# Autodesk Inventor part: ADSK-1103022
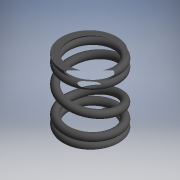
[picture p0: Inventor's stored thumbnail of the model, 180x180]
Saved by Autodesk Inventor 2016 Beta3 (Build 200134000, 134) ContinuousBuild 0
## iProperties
Shininess: 24.0
Length Units: 11272
Angle Units: 11279
Time Units: 11290
Mass Units: 11286
Length Display Precision: 4
Angle Display Precision: 2
Compacted: True
Created: 2000-03
Part Number: ADSK-1103022
Document SubType Name: Modeling
Description: UHAN SPRING #334-2
Mass: 0.0822308 g
Surface Area: 0.886826 cm^2
Volume: 0.0101771 cm^3
Density: 8.08 g/cm^3
Material: Stainless Steel
Appearance: Black
Density: 0.0
Volumn: 0.0
Area: 0.0
PropertySet Name: Model Information
Control State: 0
Master: False
Checked Out: False
Author: Autodesk, Inc.
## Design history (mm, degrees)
sketch "Sketch2"
  geometry: L1 (-14.979, -10.854)-(-14.979, 14.546); A1 r 0.254 centre (-16.757, -11.108) between (-16.503, -11.108) and (-16.757, -10.854); 1 further point
  constraints: 2 end point, 2 horizontal alignment, 2 point on circle, 2 vertical alignment, 1 centre point, 1 vertical, 5 other
  dimensions: "d0" = 25.4 distance of L1.start L1.end; "d1" = 3.048 diameter of A1.start L1; "d2" = 0.508 diameter of A1
node "Coil1" dims "d3" = 3.175 (= 0.125 x d0), "d4" = 2.921, "d5" = 12.5, "d6" = 0, "d7" = 30 deg, "d8" = 1 deg, "d9" = 30 deg, "d10" = 1 deg
workaxis "Work Axis1"
node "Coil2" dims "d11" = 0.5334 (computed from d2), "d12" = 25.4, "d13" = 20, "d14" = 0, "d15" = 90 deg, "d16" = 90 deg, "d17" = 0, "d18" = 0
  sketch "Sketch3"
    geometry: L1 (1.778, -1.011)-(1.778, 3.933) reference; C1 r 0.254 at (0, 0) reference
node "Extrusion1" dims "d19" = 25.4, "d20" = 0
  sketch "Sketch4"
    geometry: L1 (-2.213, -5.897)-(17.486, -5.897); L2 (17.486, -5.897)-(17.486, 0.254); L3 (17.486, 0.254)-(-2.213, 0.254); L4 (-2.213, 0.254)-(-2.213, -5.897); C1 r 0.254 at (0, 0) reference
    constraints: 8 end point, 2 parallel, 1 horizontal, 1 perpendicular, 1 tangent
node "Coil3" dims "d21" = 0.5334 (computed from d2), "d22" = 25.4, "d23" = 20, "d24" = 0, "d25" = 90 deg, "d26" = 90 deg, "d27" = 0, "d28" = 0
  sketch "Sketch5"
    geometry: L1 (-1.778, -3.932)-(-1.778, 1.012) reference; C1 r 0.254 at (0, 0) reference
node "Extrusion2" dims "d29" = 25.4, "d30" = 0
  sketch "Sketch6"
    geometry: L1 (7.067, 10.875)-(-19.265, 10.875); L2 (-19.265, 10.875)-(-19.265, -0.254); L3 (-19.265, -0.254)-(7.067, -0.254); L4 (7.067, -0.254)-(7.067, 10.875); C1 r 0.254 at (0, 0) reference
    constraints: 8 end point, 2 parallel, 1 horizontal, 1 perpendicular, 1 tangent
body "Solid1"
